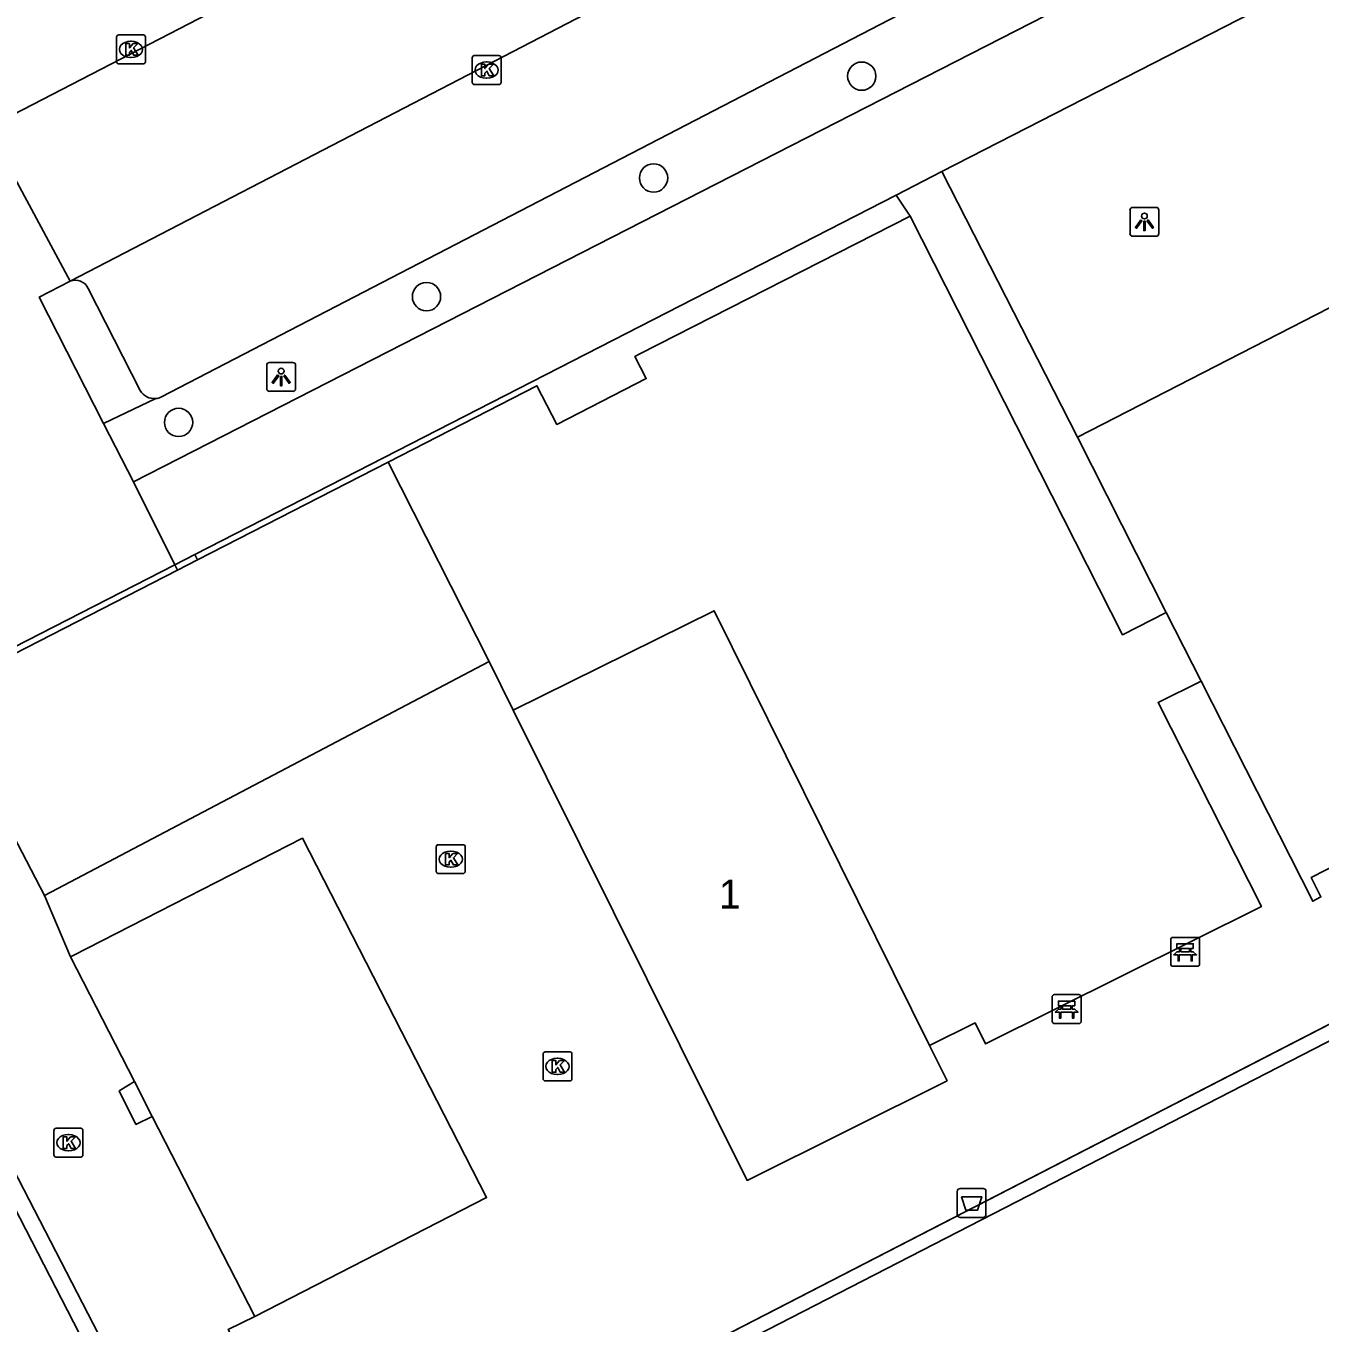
# Model space of a CAD drawing. Extents: x 158838 to 160074, y 386376 to 387776.
# Drawn here: x 159347 to 159391.72, y 387156.97 to 387201.8 of the extents above; entities that cross this region are included whole.
import ezdxf

# ---------------------------------------------------------------- set-up
doc = ezdxf.new("R2010")
doc.units = 0
for name, color, linetype in [('IMGEO_Afvalbak', 7, 'Continuous'), ('IMGEO_Bank', 7, 'Continuous'), ('IMGEO_Boom', 7, 'Continuous'), ('IMGEO_Groenvoorziening', 7, 'Continuous'), ('IMGEO_Hek', 7, 'Continuous'), ('IMGEO_Kolk', 7, 'Continuous'), ('IMGEO_Lichtpunt', 7, 'Continuous'), ('IMGEO_Pand', 7, 'Continuous'), ('IMGEO_Pand_nummerreeks', 7, 'Continuous'), ('IMGEO_Parkeervlak_gesloten', 7, 'Continuous'), ('IMGEO_Rijbaan_lokaal_open', 7, 'Continuous'), ('IMGEO_Voetpad_open', 7, 'Continuous')]:
    doc.layers.add(name, color=color, linetype=linetype)

msp = doc.modelspace()

# ---------------------------------------------------------------- linework, layer by layer
at = {"layer": 'IMGEO_Afvalbak'}
for p, q in [((159379.187, 387160.721), (159379.187, 387161.521)), ((159379.187, 387161.521), (159379.187, 387160.721)), ((159379.287, 387161.621), (159380.077, 387161.621)), ((159380.077, 387161.621), (159379.287, 387161.621)), ((159380.177, 387161.521), (159380.177, 387160.721)), ((159380.177, 387160.721), (159380.177, 387161.521)), ((159380.077, 387160.621), (159379.287, 387160.621)), ((159379.287, 387160.621), (159380.077, 387160.621))]:
    msp.add_line(p, q, dxfattribs=at)
msp.add_lwpolyline([(159379.33, 387161.335), (159380.034, 387161.335), (159379.885, 387160.865), (159379.479, 387160.865), (159379.33, 387161.335)], dxfattribs=at)
for centre, start, end in [((159379.287, 387161.521), 90, 180), ((159379.287, 387161.521), 90, 180), ((159380.077, 387161.521), 0, 90), ((159380.077, 387161.521), 360, 90), ((159379.287, 387160.721), 180, 270), ((159379.287, 387160.721), 180, 270), ((159380.077, 387160.721), 270, 0), ((159380.077, 387160.721), 270, 0)]:
    msp.add_arc(centre, 0.1, start, end, dxfattribs=at)
at = {"layer": 'IMGEO_Bank'}
for p, q in [((159386.561, 387169.375), (159386.561, 387170.216)), ((159386.561, 387170.216), (159386.561, 387169.375)), ((159386.636, 387170.3), (159387.477, 387170.3)), ((159387.477, 387170.3), (159386.636, 387170.3)), ((159386.87, 387169.806), (159386.87, 387169.912)), ((159386.914, 387169.912), (159386.914, 387169.806)), ((159387.202, 387169.918), (159386.92, 387169.918)), ((159387.208, 387169.806), (159387.208, 387169.912)), ((159387.252, 387169.912), (159387.252, 387169.806)), ((159387.561, 387170.225), (159387.561, 387169.384)), ((159387.561, 387169.384), (159387.561, 387170.225)), ((159387.258, 387169.698), (159386.865, 387169.698)), ((159386.92, 387169.8), (159387.202, 387169.8)), ((159387.486, 387169.3), (159386.645, 387169.3)), ((159386.645, 387169.3), (159387.486, 387169.3)), ((159382.466, 387167.395), (159382.466, 387168.236)), ((159382.466, 387168.236), (159382.466, 387167.395)), ((159382.541, 387168.32), (159383.382, 387168.32)), ((159383.382, 387168.32), (159382.541, 387168.32)), ((159383.466, 387168.245), (159383.466, 387167.404)), ((159383.466, 387167.404), (159383.466, 387168.245)), ((159383.163, 387167.718), (159382.77, 387167.718)), ((159382.775, 387167.826), (159382.775, 387167.932)), ((159382.819, 387167.932), (159382.819, 387167.826)), ((159383.107, 387167.938), (159382.825, 387167.938)), ((159382.825, 387167.82), (159383.107, 387167.82)), ((159383.113, 387167.826), (159383.113, 387167.932)), ((159383.157, 387167.932), (159383.157, 387167.826)), ((159383.391, 387167.32), (159382.55, 387167.32)), ((159382.55, 387167.32), (159383.391, 387167.32))]:
    msp.add_line(p, q, dxfattribs=at)
for points in [[(159386.864, 387169.918), (159386.778, 387169.918), (159386.778, 387170.079), (159387.341, 387170.079), (159387.341, 387169.918), (159387.258, 387169.918)], [(159386.808, 387169.698), (159386.666, 387169.698), (159386.778, 387169.8), (159386.864, 387169.8)], [(159386.858, 387169.691), (159386.858, 387169.484), (159386.815, 387169.484), (159386.815, 387169.691)], [(159387.258, 387169.8), (159387.341, 387169.8), (159387.453, 387169.698), (159387.314, 387169.698)], [(159387.308, 387169.691), (159387.308, 387169.484), (159387.264, 387169.484), (159387.264, 387169.691)], [(159382.769, 387167.938), (159382.683, 387167.938), (159382.683, 387168.099), (159383.246, 387168.099), (159383.246, 387167.938), (159383.163, 387167.938)], [(159382.713, 387167.718), (159382.571, 387167.718), (159382.683, 387167.82), (159382.769, 387167.82)], [(159382.763, 387167.711), (159382.763, 387167.504), (159382.72, 387167.504), (159382.72, 387167.711)], [(159383.163, 387167.82), (159383.246, 387167.82), (159383.358, 387167.718), (159383.219, 387167.718)], [(159383.213, 387167.711), (159383.213, 387167.504), (159383.169, 387167.504), (159383.169, 387167.711)]]:
    msp.add_lwpolyline(points, dxfattribs=at)
for centre, radius, start, end in [((159386.639, 387170.222), 0.0779, 92.4484, 184.2845), ((159386.639, 387170.222), 0.0779, 92.4484, 184.2845), ((159386.863, 387169.911), 0.00671, 2.8957, 87.1043), ((159386.92, 387169.911), 0.00671, 92.8957, 177.1043), ((159387.202, 387169.911), 0.00671, 2.8957, 87.1043), ((159387.259, 387169.911), 0.00671, 92.8957, 177.1043), ((159387.483, 387170.222), 0.0779, 2.4484, 94.2845), ((159387.483, 387170.222), 0.0779, 2.4484, 94.2845), ((159386.808, 387169.691), 0.00671, 2.8957, 87.1043), ((159386.865, 387169.691), 0.00671, 92.8957, 177.1043), ((159386.863, 387169.807), 0.00671, 272.8957, 357.1043), ((159386.92, 387169.807), 0.00671, 182.8957, 267.1043), ((159387.202, 387169.807), 0.00671, 272.8957, 357.1043), ((159387.259, 387169.807), 0.00671, 182.8957, 267.1043), ((159387.257, 387169.691), 0.00671, 2.8957, 87.1043), ((159387.314, 387169.691), 0.00671, 92.8957, 177.1043), ((159386.639, 387169.378), 0.0779, 182.4484, 274.2845), ((159386.639, 387169.378), 0.0779, 182.4484, 274.2845), ((159387.483, 387169.378), 0.0779, 272.4484, 4.2845), ((159387.483, 387169.378), 0.0779, 272.4484, 4.2845), ((159382.544, 387168.242), 0.0779, 92.4484, 184.2845), ((159382.544, 387168.242), 0.0779, 92.4484, 184.2845), ((159383.388, 387168.242), 0.0779, 2.4484, 94.2845), ((159383.388, 387168.242), 0.0779, 2.4484, 94.2845), ((159382.713, 387167.711), 0.00671, 2.8957, 87.1043), ((159382.77, 387167.711), 0.00671, 92.8957, 177.1043), ((159382.768, 387167.931), 0.00671, 2.8957, 87.1043), ((159382.768, 387167.827), 0.00671, 272.8957, 357.1043), ((159382.825, 387167.931), 0.00671, 92.8957, 177.1043), ((159382.825, 387167.827), 0.00671, 182.8957, 267.1043), ((159383.107, 387167.931), 0.00671, 2.8957, 87.1043), ((159383.107, 387167.827), 0.00671, 272.8957, 357.1043), ((159383.164, 387167.931), 0.00671, 92.8957, 177.1043), ((159383.164, 387167.827), 0.00671, 182.8957, 267.1043), ((159383.162, 387167.711), 0.00671, 2.8957, 87.1043), ((159383.219, 387167.711), 0.00671, 92.8957, 177.1043), ((159382.544, 387167.398), 0.0779, 182.4484, 274.2845), ((159382.544, 387167.398), 0.0779, 182.4484, 274.2845), ((159383.388, 387167.398), 0.0779, 272.4484, 4.2845), ((159383.388, 387167.398), 0.0779, 272.4484, 4.2845)]:
    msp.add_arc(centre, radius, start, end, dxfattribs=at)
at = {"layer": 'IMGEO_Boom'}
for centre in [(159375.885, 387200.064), (159368.691, 387196.545), (159360.845, 387192.443), (159352.277, 387188.096)]:
    msp.add_circle(centre, 0.489, dxfattribs=at)
at = {"layer": 'IMGEO_Groenvoorziening'}
msp.add_lwpolyline([(159351.488, 387188.921), (159349.687, 387188.056)], dxfattribs=at)
at = {"layer": 'IMGEO_Hek'}
for points in [[(159357.694, 387149.458), (159357.636, 387149.571), (159453.843, 387199.132), (159486.981, 387134.684), (159482.964, 387132.627)], [(159277.882, 387137.966), (159342.113, 387170.898), (159351.718, 387152.3)]]:
    msp.add_lwpolyline(points, dxfattribs=at)
at = {"layer": 'IMGEO_Kolk'}
for p, q in [((159350.133, 387200.563), (159350.133, 387201.415)), ((159350.208, 387201.489), (159351.06, 387201.489)), ((159350.621, 387201.269), (159350.646, 387201.269)), ((159351.134, 387201.415), (159351.134, 387200.563)), ((159351.06, 387200.489), (159350.208, 387200.489)), ((159350.644, 387200.709), (159350.619, 387200.709)), ((159362.422, 387199.849), (159362.422, 387200.701)), ((159362.497, 387200.775), (159363.349, 387200.775)), ((159362.91, 387200.555), (159362.935, 387200.555)), ((159363.423, 387200.701), (159363.423, 387199.849)), ((159362.933, 387199.995), (159362.908, 387199.995)), ((159363.349, 387199.775), (159362.497, 387199.775)), ((159361.258, 387173.502), (159362.11, 387173.502)), ((159361.183, 387172.576), (159361.183, 387173.428)), ((159361.671, 387173.282), (159361.696, 387173.282)), ((159362.184, 387173.428), (159362.184, 387172.576)), ((159361.694, 387172.722), (159361.669, 387172.722)), ((159362.11, 387172.502), (159361.258, 387172.502)), ((159364.946, 387166.34), (159365.798, 387166.34)), ((159364.871, 387165.414), (159364.871, 387166.266)), ((159365.359, 387166.12), (159365.384, 387166.12)), ((159365.872, 387166.266), (159365.872, 387165.414)), ((159365.382, 387165.56), (159365.357, 387165.56)), ((159365.798, 387165.34), (159364.946, 387165.34)), ((159347.972, 387162.777), (159347.972, 387163.629)), ((159348.047, 387163.703), (159348.899, 387163.703)), ((159348.973, 387163.629), (159348.973, 387162.777)), ((159348.46, 387163.483), (159348.485, 387163.483)), ((159348.899, 387162.703), (159348.047, 387162.703)), ((159348.483, 387162.923), (159348.458, 387162.923))]:
    msp.add_line(p, q, dxfattribs=at)
for points in [[(159350.133, 387200.563), (159350.133, 387201.415)], [(159350.208, 387201.489), (159351.06, 387201.489)], [(159351.134, 387201.415), (159351.134, 387200.563)], [(159350.454, 387201.189), (159350.577, 387201.189), (159350.577, 387201.038), (159350.707, 387201.189), (159350.871, 387201.189), (159350.725, 387201.038), (159350.878, 387200.789), (159350.726, 387200.789), (159350.641, 387200.953), (159350.577, 387200.886), (159350.577, 387200.789), (159350.454, 387200.789), (159350.454, 387201.189)], [(159351.06, 387200.489), (159350.208, 387200.489)], [(159362.422, 387199.849), (159362.422, 387200.701)], [(159362.497, 387200.775), (159363.349, 387200.775)], [(159362.743, 387200.475), (159362.866, 387200.475), (159362.866, 387200.324), (159362.996, 387200.475), (159363.16, 387200.475), (159363.014, 387200.324), (159363.167, 387200.075), (159363.015, 387200.075), (159362.93, 387200.239), (159362.866, 387200.172), (159362.866, 387200.075), (159362.743, 387200.075), (159362.743, 387200.475)], [(159363.423, 387200.701), (159363.423, 387199.849)], [(159363.349, 387199.775), (159362.497, 387199.775)], [(159361.258, 387173.502), (159362.11, 387173.502)], [(159361.183, 387172.576), (159361.183, 387173.428)], [(159361.504, 387173.202), (159361.627, 387173.202), (159361.627, 387173.051), (159361.757, 387173.202), (159361.921, 387173.202), (159361.775, 387173.051), (159361.928, 387172.802), (159361.776, 387172.802), (159361.691, 387172.966), (159361.627, 387172.899), (159361.627, 387172.802), (159361.504, 387172.802), (159361.504, 387173.202)], [(159362.184, 387173.428), (159362.184, 387172.576)], [(159362.11, 387172.502), (159361.258, 387172.502)], [(159364.946, 387166.34), (159365.798, 387166.34)], [(159364.871, 387165.414), (159364.871, 387166.266)], [(159365.192, 387166.04), (159365.315, 387166.04), (159365.315, 387165.889), (159365.445, 387166.04), (159365.609, 387166.04), (159365.463, 387165.889), (159365.616, 387165.64), (159365.464, 387165.64), (159365.379, 387165.804), (159365.315, 387165.737), (159365.315, 387165.64), (159365.192, 387165.64), (159365.192, 387166.04)], [(159365.872, 387166.266), (159365.872, 387165.414)], [(159365.798, 387165.34), (159364.946, 387165.34)], [(159347.972, 387162.777), (159347.972, 387163.629)], [(159348.047, 387163.703), (159348.899, 387163.703)], [(159348.973, 387163.629), (159348.973, 387162.777)], [(159348.293, 387163.403), (159348.416, 387163.403), (159348.416, 387163.252), (159348.546, 387163.403), (159348.71, 387163.403), (159348.564, 387163.252), (159348.717, 387163.003), (159348.565, 387163.003), (159348.48, 387163.167), (159348.416, 387163.1), (159348.416, 387163.003), (159348.293, 387163.003), (159348.293, 387163.403)], [(159348.899, 387162.703), (159348.047, 387162.703)]]:
    msp.add_lwpolyline(points, dxfattribs=at)
for centre, start, end in [((159350.21, 387201.413), 91.552, 178.448), ((159350.21, 387201.413), 91.552, 178.448), ((159351.058, 387201.413), 1.552, 88.448), ((159351.058, 387201.413), 1.552, 88.448), ((159350.21, 387200.565), 181.552, 268.448), ((159350.21, 387200.565), 181.552, 268.448), ((159351.058, 387200.565), 271.552, 358.448), ((159351.058, 387200.565), 271.552, 358.448), ((159362.499, 387200.699), 91.552, 178.448), ((159362.499, 387200.699), 91.552, 178.448), ((159363.347, 387200.699), 1.552, 88.448), ((159363.347, 387200.699), 1.552, 88.448), ((159362.499, 387199.851), 181.552, 268.448), ((159362.499, 387199.851), 181.552, 268.448), ((159363.347, 387199.851), 271.552, 358.448), ((159363.347, 387199.851), 271.552, 358.448), ((159361.26, 387173.426), 91.552, 178.448), ((159361.26, 387173.426), 91.552, 178.448), ((159362.108, 387173.426), 1.552, 88.448), ((159362.108, 387173.426), 1.552, 88.448), ((159361.26, 387172.578), 181.552, 268.448), ((159361.26, 387172.578), 181.552, 268.448), ((159362.108, 387172.578), 271.552, 358.448), ((159362.108, 387172.578), 271.552, 358.448), ((159364.948, 387166.264), 91.552, 178.448), ((159364.948, 387166.264), 91.552, 178.448), ((159365.796, 387166.264), 1.552, 88.448), ((159365.796, 387166.264), 1.552, 88.448), ((159364.948, 387165.416), 181.552, 268.448), ((159364.948, 387165.416), 181.552, 268.448), ((159365.796, 387165.416), 271.552, 358.448), ((159365.796, 387165.416), 271.552, 358.448), ((159348.049, 387163.627), 91.552, 178.448), ((159348.049, 387163.627), 91.552, 178.448), ((159348.897, 387163.627), 1.552, 88.448), ((159348.897, 387163.627), 1.552, 88.448), ((159348.049, 387162.779), 181.552, 268.448), ((159348.049, 387162.779), 181.552, 268.448), ((159348.897, 387162.779), 271.552, 358.448), ((159348.897, 387162.779), 271.552, 358.448)]:
    msp.add_arc(centre, 0.0765, start, end, dxfattribs=at)
for centre, major_axis, ratio, start_param, end_param in [((159350.62, 387200.989), (-0.387, 0.002), 0.722429, 4.712389, 7.853982), ((159350.645, 387200.989), (-0.39, 0.002), 0.717154, 1.570796, 4.712389), ((159362.909, 387200.275), (-0.387, 0.002), 0.722429, 4.712389, 7.853982), ((159362.934, 387200.275), (-0.39, 0.002), 0.717154, 1.570796, 4.712389), ((159361.67, 387173.002), (-0.387, 0.002), 0.722429, 4.712389, 7.853982), ((159361.695, 387173.002), (-0.39, 0.002), 0.717154, 1.570796, 4.712389), ((159365.358, 387165.84), (-0.387, 0.002), 0.722429, 4.712389, 7.853982), ((159365.383, 387165.84), (-0.39, 0.002), 0.717154, 1.570796, 4.712389), ((159348.459, 387163.203), (-0.387, 0.002), 0.722429, 4.712389, 7.853982), ((159348.484, 387163.203), (-0.39, 0.002), 0.717154, 1.570796, 4.712389)]:
    msp.add_ellipse(centre, major_axis=major_axis, ratio=ratio, start_param=start_param, end_param=end_param, dxfattribs=at)
at = {"layer": 'IMGEO_Lichtpunt'}
for p, q in [((159385.155, 387195.432), (159385.155, 387194.625)), ((159385.155, 387195.432), (159385.155, 387194.625)), ((159386.057, 387195.527), (159385.249, 387195.527)), ((159386.057, 387195.527), (159385.249, 387195.527)), ((159386.151, 387194.625), (159386.151, 387195.432)), ((159386.151, 387194.625), (159386.151, 387195.432)), ((159385.249, 387194.531), (159386.057, 387194.531)), ((159385.249, 387194.531), (159386.057, 387194.531)), ((159355.324, 387190.072), (159355.324, 387189.265)), ((159355.324, 387190.072), (159355.324, 387189.265)), ((159356.226, 387190.167), (159355.418, 387190.167)), ((159356.226, 387190.167), (159355.418, 387190.167)), ((159356.32, 387189.265), (159356.32, 387190.072)), ((159356.32, 387189.265), (159356.32, 387190.072)), ((159355.418, 387189.171), (159356.226, 387189.171)), ((159355.418, 387189.171), (159356.226, 387189.171))]:
    msp.add_line(p, q, dxfattribs=at)
for points in [[(159385.529, 387195.096), (159385.568, 387195.068), (159385.38, 387194.806), (159385.342, 387194.833), (159385.529, 387195.096)], [(159385.631, 387195.048), (159385.678, 387195.048), (159385.678, 387194.726), (159385.631, 387194.726), (159385.631, 387195.048)], [(159385.741, 387195.068), (159385.779, 387195.095), (159385.966, 387194.833), (159385.927, 387194.805), (159385.741, 387195.068)], [(159355.698, 387189.736), (159355.737, 387189.708), (159355.549, 387189.446), (159355.511, 387189.473), (159355.698, 387189.736)], [(159355.8, 387189.688), (159355.847, 387189.688), (159355.847, 387189.366), (159355.8, 387189.366), (159355.8, 387189.688)], [(159355.91, 387189.708), (159355.948, 387189.735), (159356.135, 387189.473), (159356.096, 387189.445), (159355.91, 387189.708)]]:
    msp.add_lwpolyline(points, dxfattribs=at)
for centre in [(159385.654, 387195.23), (159355.823, 387189.87)]:
    msp.add_circle(centre, 0.0994, dxfattribs=at)
for centre, start, end in [((159385.249, 387195.432), 90, 180), ((159385.249, 387195.432), 90, 180), ((159386.057, 387195.432), 0, 90), ((159386.057, 387195.432), 0, 90), ((159385.249, 387194.625), 180, 270), ((159385.249, 387194.625), 180, 270), ((159386.057, 387194.625), 270, 0), ((159386.057, 387194.625), 270, 360), ((159355.418, 387190.072), 90, 180), ((159355.418, 387190.072), 90, 180), ((159356.226, 387190.072), 0, 90), ((159356.226, 387190.072), 0, 90), ((159355.418, 387189.265), 180, 270), ((159355.418, 387189.265), 180, 270), ((159356.226, 387189.265), 270, 0), ((159356.226, 387189.265), 270, 360)]:
    msp.add_arc(centre, 0.0946, start, end, dxfattribs=at)
at = {"layer": 'IMGEO_Pand'}
for points in [[(159416.154, 387184.165), (159416.337, 387184.259), (159408.099, 387200.29), (159383.337, 387187.582)], [(159359.522, 387186.728), (159364.662, 387189.365), (159365.349, 387188.026), (159368.438, 387189.612), (159368.039, 387190.374), (159368.217, 387190.465), (159377.564, 387195.228)], [(159386.407, 387181.529), (159384.893, 387180.758), (159377.564, 387195.228)], [(159383.337, 387187.582), (159386.407, 387181.529)], [(159352.937, 387183.349), (159359.522, 387186.728)], [(159363.013, 387179.836), (159359.522, 387186.728)], [(159387.61, 387179.158), (159391.469, 387171.55), (159391.753, 387171.696), (159391.411, 387172.363), (159415.709, 387184.78), (159416.052, 387184.112), (159416.154, 387184.165)], [(159352.242, 387182.992), (159352.937, 387183.349)], [(159352.242, 387182.992), (159343.975, 387178.751), (159346.089, 387174.713), (159347.641, 387171.75)], [(159378.228, 387166.559), (159370.787, 387181.589), (159363.842, 387178.146)], [(159387.61, 387179.158), (159386.407, 387181.529)], [(159347.641, 387171.75), (159363.013, 387179.836)], [(159363.013, 387179.836), (159363.842, 387178.146)], [(159378.228, 387166.559), (159379.804, 387167.343), (159380.165, 387166.618), (159389.697, 387171.362), (159386.123, 387178.418), (159387.61, 387179.158)], [(159363.842, 387178.146), (159371.923, 387161.901), (159378.834, 387165.341), (159378.228, 387166.559)], [(159354.907, 387157.199), (159362.921, 387161.303), (159356.554, 387173.733), (159348.636, 387169.677), (159348.541, 387169.628)], [(159350.749, 387165.318), (159348.541, 387169.628)], [(159350.749, 387165.318), (159351.369, 387164.106)], [(159354.907, 387157.199), (159351.369, 387164.106)]]:
    msp.add_lwpolyline(points, dxfattribs=at)
at = {"layer": 'IMGEO_Parkeervlak_gesloten'}
for points in [[(159351.663, 387188.964), (159387.345, 387207.473)], [(159349.155, 387192.727), (159350.955, 387189.198)]]:
    msp.add_lwpolyline(points, dxfattribs=at)
for centre, radius, start, end in [((159348.709, 387192.525), 0.49, 24.4065, 111.6445), ((159351.44, 387189.48), 0.561, 210.193, 274.8852), ((159351.45, 387189.455), 0.535, 274.1099, 293.4999)]:
    msp.add_arc(centre, radius, start, end, dxfattribs=at)
at = {"layer": 'IMGEO_Rijbaan_lokaal_open'}
for points in [[(159382.33, 387217.246), (159345.873, 387198.377)], [(159385.06, 387211.926), (159348.528, 387192.98)], [(159345.683, 387198.254), (159348.528, 387192.98)]]:
    msp.add_lwpolyline(points, dxfattribs=at)
at = {"layer": 'IMGEO_Voetpad_open'}
for points in [[(159378.658, 387196.768), (159407.952, 387211.785)], [(159388.438, 387205.343), (159350.715, 387186.039)], [(159453.705, 387198.411), (159450.209, 387196.614), (159358.268, 387149.353), (159390.832, 387085.959), (159482.689, 387133.165), (159486.302, 387135.022), (159453.705, 387198.411)], [(159377.069, 387195.954), (159378.658, 387196.768)], [(159378.658, 387196.768), (159383.337, 387187.582)], [(159377.069, 387195.954), (159352.842, 387183.536)], [(159377.564, 387195.228), (159377.069, 387195.954)], [(159348.528, 387192.98), (159347.46, 387192.427), (159349.687, 387188.056)], [(159349.687, 387188.056), (159350.715, 387186.039)], [(159350.715, 387186.039), (159352.148, 387183.18)], [(159352.842, 387183.536), (159352.148, 387183.18)], [(159352.937, 387183.349), (159352.842, 387183.536)], [(159352.148, 387183.18), (159339.149, 387176.517)], [(159352.148, 387183.18), (159352.242, 387182.992)], [(159417.921, 387180.627), (159357.636, 387149.571)], [(159348.541, 387169.628), (159347.641, 387171.75)], [(159342.113, 387170.898), (159351.718, 387152.3)], [(159312.621, 387071.338), (159327.522, 387042.338), (159390.868, 387074.876), (159369.62, 387116.222), (159341.852, 387170.195), (159341.327, 387169.926), (159306.253, 387151.947), (159278.51, 387137.726), (159293.833, 387107.905)], [(159351.369, 387164.106), (159350.802, 387163.836), (159350.225, 387164.992), (159350.749, 387165.318)], [(159357.636, 387149.571), (159357.088, 387150.658), (159353.996, 387156.748), (159354.907, 387157.199)]]:
    msp.add_lwpolyline(points, dxfattribs=at)

# ---------------------------------------------------------------- texts
at = {"layer": 'IMGEO_Pand_nummerreeks'}
msp.add_text('1', height=1, dxfattribs=at).set_placement((159370.955, 387171.295))

doc.saveas('drawing.dxf')
